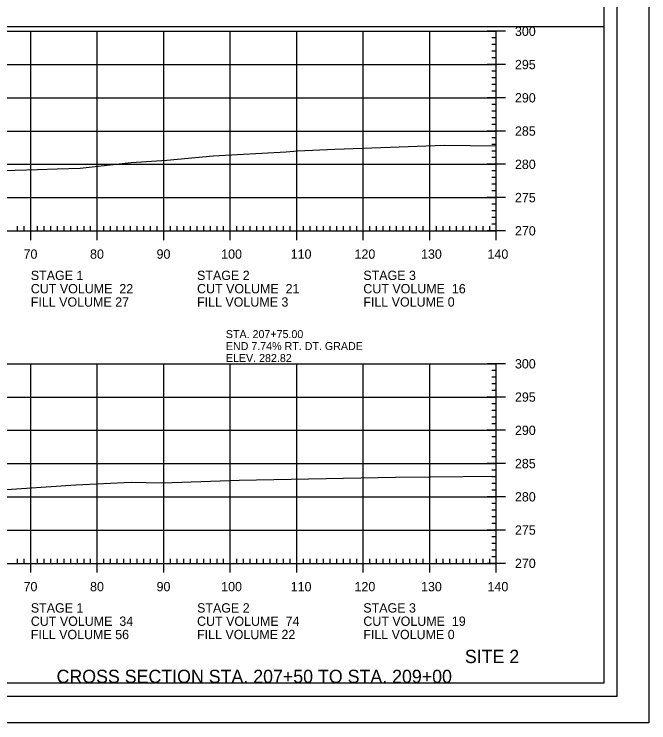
# Model space of a CAD drawing. Extents: x 1368713 to 1370673, y 380279 to 380950.
# Drawn here: x 1370577.1 to 1370672.6, y 380737.1 to 380843.7 of the extents above; entities that cross this region are included whole.
import ezdxf

# ---------------------------------------------------------------- set-up
doc = ezdxf.new("R2010")
doc.units = 0
for name, color, linetype in [('Notes', 7, 'Continuous'), ('R_Axis', 7, 'Continuous'), ('R_Axis Annot', 7, 'Continuous'), ('R_Border', 7, 'Continuous'), ('R_Draft', 7, 'Continuous'), ('R_Exist Surface', 7, 'Continuous'), ('R_Grid', 7, 'Continuous'), ('R_No Plot', 7, 'Continuous')]:
    doc.layers.add(name, color=color, linetype=linetype)

msp = doc.modelspace()

# ---------------------------------------------------------------- linework, layer by layer
at = {"layer": 'R_Axis'}
for p, q in [((1370651.03, 380841.09), (1370648.23, 380841.09)), ((1370649.63, 380811.09), (1370649.63, 380841.09)), ((1370649.63, 380840.09), (1370648.93, 380840.09)), ((1370649.63, 380839.09), (1370648.93, 380839.09)), ((1370649.63, 380838.09), (1370648.93, 380838.09)), ((1370649.63, 380837.09), (1370648.93, 380837.09)), ((1370651.03, 380836.09), (1370648.23, 380836.09)), ((1370649.63, 380835.09), (1370648.93, 380835.09)), ((1370649.63, 380834.09), (1370648.93, 380834.09)), ((1370649.63, 380833.09), (1370648.93, 380833.09)), ((1370651.03, 380831.09), (1370648.23, 380831.09)), ((1370649.63, 380832.09), (1370648.93, 380832.09)), ((1370649.63, 380830.09), (1370648.93, 380830.09)), ((1370649.63, 380829.09), (1370648.93, 380829.09)), ((1370649.63, 380828.09), (1370648.93, 380828.09)), ((1370649.63, 380827.09), (1370648.93, 380827.09)), ((1370651.03, 380826.09), (1370648.23, 380826.09)), ((1370649.63, 380825.09), (1370648.93, 380825.09)), ((1370649.63, 380824.09), (1370648.93, 380824.09)), ((1370649.63, 380823.09), (1370648.93, 380823.09)), ((1370649.63, 380822.09), (1370648.93, 380822.09)), ((1370651.03, 380821.09), (1370648.23, 380821.09)), ((1370649.63, 380820.09), (1370648.93, 380820.09)), ((1370649.63, 380819.09), (1370648.93, 380819.09)), ((1370649.63, 380818.09), (1370648.93, 380818.09)), ((1370649.63, 380817.09), (1370648.93, 380817.09)), ((1370651.03, 380816.09), (1370648.23, 380816.09)), ((1370649.63, 380815.09), (1370648.93, 380815.09)), ((1370649.63, 380814.09), (1370648.93, 380814.09)), ((1370649.63, 380813.09), (1370648.93, 380813.09)), ((1370579.63, 380809.69), (1370579.63, 380812.49)), ((1370589.63, 380809.69), (1370589.63, 380812.49)), ((1370599.63, 380809.69), (1370599.63, 380812.49)), ((1370609.63, 380809.69), (1370609.63, 380812.49)), ((1370619.63, 380809.69), (1370619.63, 380812.49)), ((1370629.63, 380809.69), (1370629.63, 380812.49)), ((1370639.63, 380809.69), (1370639.63, 380812.49)), ((1370649.63, 380812.09), (1370648.93, 380812.09)), ((1370649.63, 380809.69), (1370649.63, 380812.49)), ((1370369.63, 380811.09), (1370649.63, 380811.09)), ((1370577.63, 380811.09), (1370577.63, 380811.79)), ((1370578.63, 380811.09), (1370578.63, 380811.79)), ((1370580.63, 380811.09), (1370580.63, 380811.79)), ((1370581.63, 380811.09), (1370581.63, 380811.79)), ((1370582.63, 380811.09), (1370582.63, 380811.79)), ((1370583.63, 380811.09), (1370583.63, 380811.79)), ((1370584.63, 380811.09), (1370584.63, 380811.79)), ((1370585.63, 380811.09), (1370585.63, 380811.79)), ((1370586.63, 380811.09), (1370586.63, 380811.79)), ((1370587.63, 380811.09), (1370587.63, 380811.79)), ((1370588.63, 380811.09), (1370588.63, 380811.79)), ((1370590.63, 380811.09), (1370590.63, 380811.79)), ((1370591.63, 380811.09), (1370591.63, 380811.79)), ((1370592.63, 380811.09), (1370592.63, 380811.79)), ((1370593.63, 380811.09), (1370593.63, 380811.79)), ((1370594.63, 380811.09), (1370594.63, 380811.79)), ((1370595.63, 380811.09), (1370595.63, 380811.79)), ((1370596.63, 380811.09), (1370596.63, 380811.79)), ((1370597.63, 380811.09), (1370597.63, 380811.79)), ((1370598.63, 380811.09), (1370598.63, 380811.79)), ((1370600.63, 380811.09), (1370600.63, 380811.79)), ((1370601.63, 380811.09), (1370601.63, 380811.79)), ((1370602.63, 380811.09), (1370602.63, 380811.79)), ((1370603.63, 380811.09), (1370603.63, 380811.79)), ((1370604.63, 380811.09), (1370604.63, 380811.79)), ((1370605.63, 380811.09), (1370605.63, 380811.79)), ((1370606.63, 380811.09), (1370606.63, 380811.79)), ((1370607.63, 380811.09), (1370607.63, 380811.79)), ((1370608.63, 380811.09), (1370608.63, 380811.79)), ((1370610.63, 380811.09), (1370610.63, 380811.79)), ((1370611.63, 380811.09), (1370611.63, 380811.79)), ((1370612.63, 380811.09), (1370612.63, 380811.79)), ((1370613.63, 380811.09), (1370613.63, 380811.79)), ((1370614.63, 380811.09), (1370614.63, 380811.79)), ((1370615.63, 380811.09), (1370615.63, 380811.79)), ((1370616.63, 380811.09), (1370616.63, 380811.79)), ((1370617.63, 380811.09), (1370617.63, 380811.79)), ((1370618.63, 380811.09), (1370618.63, 380811.79)), ((1370620.63, 380811.09), (1370620.63, 380811.79)), ((1370621.63, 380811.09), (1370621.63, 380811.79)), ((1370622.63, 380811.09), (1370622.63, 380811.79)), ((1370623.63, 380811.09), (1370623.63, 380811.79)), ((1370624.63, 380811.09), (1370624.63, 380811.79)), ((1370625.63, 380811.09), (1370625.63, 380811.79)), ((1370626.63, 380811.09), (1370626.63, 380811.79)), ((1370627.63, 380811.09), (1370627.63, 380811.79)), ((1370628.63, 380811.09), (1370628.63, 380811.79)), ((1370630.63, 380811.09), (1370630.63, 380811.79)), ((1370631.63, 380811.09), (1370631.63, 380811.79)), ((1370632.63, 380811.09), (1370632.63, 380811.79)), ((1370633.63, 380811.09), (1370633.63, 380811.79)), ((1370634.63, 380811.09), (1370634.63, 380811.79)), ((1370635.63, 380811.09), (1370635.63, 380811.79)), ((1370636.63, 380811.09), (1370636.63, 380811.79)), ((1370637.63, 380811.09), (1370637.63, 380811.79)), ((1370638.63, 380811.09), (1370638.63, 380811.79)), ((1370640.63, 380811.09), (1370640.63, 380811.79)), ((1370641.63, 380811.09), (1370641.63, 380811.79)), ((1370642.63, 380811.09), (1370642.63, 380811.79)), ((1370643.63, 380811.09), (1370643.63, 380811.79)), ((1370644.63, 380811.09), (1370644.63, 380811.79)), ((1370645.63, 380811.09), (1370645.63, 380811.79)), ((1370646.63, 380811.09), (1370646.63, 380811.79)), ((1370647.63, 380811.09), (1370647.63, 380811.79)), ((1370651.03, 380811.09), (1370648.23, 380811.09)), ((1370648.63, 380811.09), (1370648.63, 380811.79)), ((1370651.03, 380791.09), (1370648.23, 380791.09)), ((1370649.63, 380761.09), (1370649.63, 380791.09)), ((1370649.63, 380790.09), (1370648.93, 380790.09)), ((1370649.63, 380789.09), (1370648.93, 380789.09)), ((1370649.63, 380788.09), (1370648.93, 380788.09)), ((1370649.63, 380787.09), (1370648.93, 380787.09)), ((1370651.03, 380786.09), (1370648.23, 380786.09)), ((1370649.63, 380785.09), (1370648.93, 380785.09)), ((1370649.63, 380784.09), (1370648.93, 380784.09)), ((1370649.63, 380783.09), (1370648.93, 380783.09)), ((1370649.63, 380782.09), (1370648.93, 380782.09)), ((1370651.03, 380781.09), (1370648.23, 380781.09)), ((1370649.63, 380780.09), (1370648.93, 380780.09)), ((1370649.63, 380779.09), (1370648.93, 380779.09)), ((1370649.63, 380778.09), (1370648.93, 380778.09)), ((1370649.63, 380777.09), (1370648.93, 380777.09)), ((1370651.03, 380776.09), (1370648.23, 380776.09)), ((1370649.63, 380775.09), (1370648.93, 380775.09)), ((1370649.63, 380774.09), (1370648.93, 380774.09)), ((1370649.63, 380773.09), (1370648.93, 380773.09)), ((1370649.63, 380772.09), (1370648.93, 380772.09)), ((1370651.03, 380771.09), (1370648.23, 380771.09)), ((1370649.63, 380770.09), (1370648.93, 380770.09)), ((1370649.63, 380769.09), (1370648.93, 380769.09)), ((1370649.63, 380768.09), (1370648.93, 380768.09)), ((1370651.03, 380766.09), (1370648.23, 380766.09)), ((1370649.63, 380767.09), (1370648.93, 380767.09)), ((1370649.63, 380765.09), (1370648.93, 380765.09)), ((1370649.63, 380764.09), (1370648.93, 380764.09)), ((1370649.63, 380763.09), (1370648.93, 380763.09)), ((1370577.63, 380761.09), (1370577.63, 380761.79)), ((1370578.63, 380761.09), (1370578.63, 380761.79)), ((1370579.63, 380759.69), (1370579.63, 380762.49)), ((1370580.63, 380761.09), (1370580.63, 380761.79)), ((1370581.63, 380761.09), (1370581.63, 380761.79)), ((1370582.63, 380761.09), (1370582.63, 380761.79)), ((1370583.63, 380761.09), (1370583.63, 380761.79)), ((1370584.63, 380761.09), (1370584.63, 380761.79)), ((1370585.63, 380761.09), (1370585.63, 380761.79)), ((1370586.63, 380761.09), (1370586.63, 380761.79)), ((1370587.63, 380761.09), (1370587.63, 380761.79)), ((1370588.63, 380761.09), (1370588.63, 380761.79)), ((1370589.63, 380759.69), (1370589.63, 380762.49)), ((1370590.63, 380761.09), (1370590.63, 380761.79)), ((1370591.63, 380761.09), (1370591.63, 380761.79)), ((1370592.63, 380761.09), (1370592.63, 380761.79)), ((1370593.63, 380761.09), (1370593.63, 380761.79)), ((1370594.63, 380761.09), (1370594.63, 380761.79)), ((1370595.63, 380761.09), (1370595.63, 380761.79)), ((1370596.63, 380761.09), (1370596.63, 380761.79)), ((1370597.63, 380761.09), (1370597.63, 380761.79)), ((1370598.63, 380761.09), (1370598.63, 380761.79)), ((1370599.63, 380759.69), (1370599.63, 380762.49)), ((1370600.63, 380761.09), (1370600.63, 380761.79)), ((1370601.63, 380761.09), (1370601.63, 380761.79)), ((1370602.63, 380761.09), (1370602.63, 380761.79)), ((1370603.63, 380761.09), (1370603.63, 380761.79)), ((1370604.63, 380761.09), (1370604.63, 380761.79)), ((1370605.63, 380761.09), (1370605.63, 380761.79)), ((1370606.63, 380761.09), (1370606.63, 380761.79)), ((1370607.63, 380761.09), (1370607.63, 380761.79)), ((1370608.63, 380761.09), (1370608.63, 380761.79)), ((1370609.63, 380759.69), (1370609.63, 380762.49)), ((1370610.63, 380761.09), (1370610.63, 380761.79)), ((1370611.63, 380761.09), (1370611.63, 380761.79)), ((1370612.63, 380761.09), (1370612.63, 380761.79)), ((1370613.63, 380761.09), (1370613.63, 380761.79)), ((1370614.63, 380761.09), (1370614.63, 380761.79)), ((1370615.63, 380761.09), (1370615.63, 380761.79)), ((1370616.63, 380761.09), (1370616.63, 380761.79)), ((1370617.63, 380761.09), (1370617.63, 380761.79)), ((1370618.63, 380761.09), (1370618.63, 380761.79)), ((1370619.63, 380759.69), (1370619.63, 380762.49)), ((1370620.63, 380761.09), (1370620.63, 380761.79)), ((1370621.63, 380761.09), (1370621.63, 380761.79)), ((1370622.63, 380761.09), (1370622.63, 380761.79)), ((1370623.63, 380761.09), (1370623.63, 380761.79)), ((1370624.63, 380761.09), (1370624.63, 380761.79)), ((1370625.63, 380761.09), (1370625.63, 380761.79)), ((1370626.63, 380761.09), (1370626.63, 380761.79)), ((1370627.63, 380761.09), (1370627.63, 380761.79)), ((1370628.63, 380761.09), (1370628.63, 380761.79)), ((1370629.63, 380759.69), (1370629.63, 380762.49)), ((1370630.63, 380761.09), (1370630.63, 380761.79)), ((1370631.63, 380761.09), (1370631.63, 380761.79)), ((1370632.63, 380761.09), (1370632.63, 380761.79)), ((1370633.63, 380761.09), (1370633.63, 380761.79)), ((1370634.63, 380761.09), (1370634.63, 380761.79)), ((1370635.63, 380761.09), (1370635.63, 380761.79)), ((1370636.63, 380761.09), (1370636.63, 380761.79)), ((1370637.63, 380761.09), (1370637.63, 380761.79)), ((1370638.63, 380761.09), (1370638.63, 380761.79)), ((1370639.63, 380759.69), (1370639.63, 380762.49)), ((1370640.63, 380761.09), (1370640.63, 380761.79)), ((1370641.63, 380761.09), (1370641.63, 380761.79)), ((1370642.63, 380761.09), (1370642.63, 380761.79)), ((1370643.63, 380761.09), (1370643.63, 380761.79)), ((1370644.63, 380761.09), (1370644.63, 380761.79)), ((1370645.63, 380761.09), (1370645.63, 380761.79)), ((1370646.63, 380761.09), (1370646.63, 380761.79)), ((1370647.63, 380761.09), (1370647.63, 380761.79)), ((1370648.63, 380761.09), (1370648.63, 380761.79)), ((1370649.63, 380762.09), (1370648.93, 380762.09)), ((1370649.63, 380759.69), (1370649.63, 380762.49)), ((1370369.63, 380761.09), (1370649.63, 380761.09)), ((1370651.03, 380761.09), (1370648.23, 380761.09))]:
    msp.add_line(p, q, dxfattribs=at)
at = {"layer": 'R_Border'}
for q in [(1370667.81, 380946.55), (1370351.63, 380741.09)]:
    msp.add_line((1370667.81, 380741.09), q, dxfattribs=at)
at = {"layer": 'R_Exist Surface'}
for points in [[(1370575.63, 380820.15), (1370580.65, 380820.29), (1370583.58, 380820.41), (1370587.03, 380820.52), (1370594.73, 380821.35), (1370600.09, 380821.71), (1370607.06, 380822.34), (1370618.03, 380822.97), (1370619.74, 380823.1), (1370625.35, 380823.39), (1370633.66, 380823.67), (1370641.77, 380823.95), (1370649.63, 380823.86)], [(1370574.45, 380772.07), (1370586.38, 380772.89), (1370594.7, 380773.3), (1370599.22, 380773.18), (1370600.9, 380773.24), (1370610.98, 380773.6), (1370634.47, 380774.05), (1370639.75, 380774.1), (1370649.63, 380774.2)]]:
    msp.add_lwpolyline(points, dxfattribs=at)
at = {"layer": 'R_Grid'}
for p, q in [((1370369.63, 380841.09), (1370649.63, 380841.09)), ((1370579.63, 380811.09), (1370579.63, 380841.09)), ((1370589.63, 380811.09), (1370589.63, 380841.09)), ((1370599.63, 380811.09), (1370599.63, 380841.09)), ((1370609.63, 380811.09), (1370609.63, 380841.09)), ((1370619.63, 380811.09), (1370619.63, 380841.09)), ((1370629.63, 380811.09), (1370629.63, 380841.09)), ((1370639.63, 380811.09), (1370639.63, 380841.09)), ((1370649.63, 380811.09), (1370649.63, 380841.09)), ((1370369.63, 380836.09), (1370649.63, 380836.09)), ((1370369.63, 380831.09), (1370649.63, 380831.09)), ((1370369.63, 380826.09), (1370649.63, 380826.09)), ((1370369.63, 380821.09), (1370649.63, 380821.09)), ((1370369.63, 380816.09), (1370649.63, 380816.09)), ((1370369.63, 380811.09), (1370649.63, 380811.09)), ((1370369.63, 380791.09), (1370649.63, 380791.09)), ((1370579.63, 380761.09), (1370579.63, 380791.09)), ((1370589.63, 380761.09), (1370589.63, 380791.09)), ((1370599.63, 380761.09), (1370599.63, 380791.09)), ((1370609.63, 380761.09), (1370609.63, 380791.09)), ((1370619.63, 380761.09), (1370619.63, 380791.09)), ((1370629.63, 380761.09), (1370629.63, 380791.09)), ((1370639.63, 380761.09), (1370639.63, 380791.09)), ((1370649.63, 380761.09), (1370649.63, 380791.09)), ((1370369.63, 380786.09), (1370649.63, 380786.09)), ((1370369.63, 380781.09), (1370649.63, 380781.09)), ((1370369.63, 380776.09), (1370649.63, 380776.09)), ((1370369.63, 380771.09), (1370649.63, 380771.09)), ((1370369.63, 380766.09), (1370649.63, 380766.09)), ((1370369.63, 380761.09), (1370649.63, 380761.09))]:
    msp.add_line(p, q, dxfattribs=at)
at = {"layer": 'R_No Plot'}
for points in [[(1370339.22, 380950.45), (1370672.56, 380950.45), (1370672.56, 380737.11), (1370339.22, 380737.11)], [(1370353.63, 380944.55), (1370603.17, 380944.55), (1370603.17, 380934.67), (1370620.71, 380934.67), (1370644.81, 380934.67), (1370644.81, 380912.34), (1370665.81, 380912.34), (1370665.81, 380743.09), (1370353.63, 380743.09)], [(1370353.63, 380841.82), (1370665.81, 380841.82), (1370665.81, 380743.09), (1370353.63, 380743.09)]]:
    msp.add_lwpolyline(points, close=True, dxfattribs=at)

# ---------------------------------------------------------------- texts
at = {"layer": 'Notes'}
for s, p in [('STA. 207+75.00', (1370608.96, 380794.96)), ('END 7.74% RT. DT. GRADE', (1370608.96, 380793.16)), ('ELEV. 282.82', (1370608.96, 380791.36))]:
    msp.add_text(s, height=1.2, dxfattribs=at).set_placement(p)
at = {"layer": 'R_Axis Annot'}
for s, p in [('300', (1370652.43, 380840.39)), ('295', (1370652.43, 380835.39)), ('290', (1370652.43, 380830.39)), ('285', (1370652.43, 380825.39)), ('280', (1370652.43, 380820.39)), ('275', (1370652.43, 380815.39)), ('270', (1370652.43, 380810.39)), ('70', (1370578.54, 380806.89)), ('80', (1370588.54, 380806.89)), ('90', (1370598.54, 380806.89)), ('100', (1370608.26, 380806.89)), ('110', (1370618.71, 380806.89)), ('120', (1370628.31, 380806.89)), ('130', (1370638.31, 380806.89)), ('140', (1370648.31, 380806.89)), ('STAGE 1', (1370579.63, 380803.69)), ('STAGE 2', (1370604.63, 380803.69)), ('STAGE 3', (1370629.63, 380803.69)), ('CUT VOLUME  22', (1370579.63, 380801.69)), ('CUT VOLUME  21', (1370604.63, 380801.69)), ('CUT VOLUME  16', (1370629.63, 380801.69)), ('FILL VOLUME 27', (1370579.63, 380799.69)), ('FILL VOLUME 3', (1370604.63, 380799.69)), ('FILL VOLUME 0', (1370629.63, 380799.69)), ('300', (1370652.43, 380790.39)), ('295', (1370652.43, 380785.39)), ('290', (1370652.43, 380780.39)), ('285', (1370652.43, 380775.39)), ('280', (1370652.43, 380770.39)), ('275', (1370652.43, 380765.39)), ('270', (1370652.43, 380760.39)), ('70', (1370578.54, 380756.89)), ('80', (1370588.54, 380756.89)), ('90', (1370598.54, 380756.89)), ('100', (1370608.26, 380756.89)), ('110', (1370618.71, 380756.89)), ('120', (1370628.31, 380756.89)), ('130', (1370638.31, 380756.89)), ('140', (1370648.31, 380756.89)), ('STAGE 1', (1370579.63, 380753.69)), ('STAGE 2', (1370604.63, 380753.69)), ('STAGE 3', (1370629.63, 380753.69)), ('CUT VOLUME  34', (1370579.63, 380751.69)), ('CUT VOLUME  74', (1370604.63, 380751.69)), ('CUT VOLUME  19', (1370629.63, 380751.69)), ('FILL VOLUME 56', (1370579.63, 380749.69)), ('FILL VOLUME 22', (1370604.63, 380749.69)), ('FILL VOLUME 0', (1370629.63, 380749.69))]:
    msp.add_text(s, height=1.4, dxfattribs=at).set_placement(p)
at = {"layer": 'R_Draft'}
for s, p in [('SITE 2', (1370644.9, 380746.09)), ('CROSS SECTION STA. 207+50 TO STA. 209+00', (1370583.5, 380743.09))]:
    msp.add_text(s, height=2, dxfattribs=at).set_placement(p)

doc.saveas('drawing.dxf')
